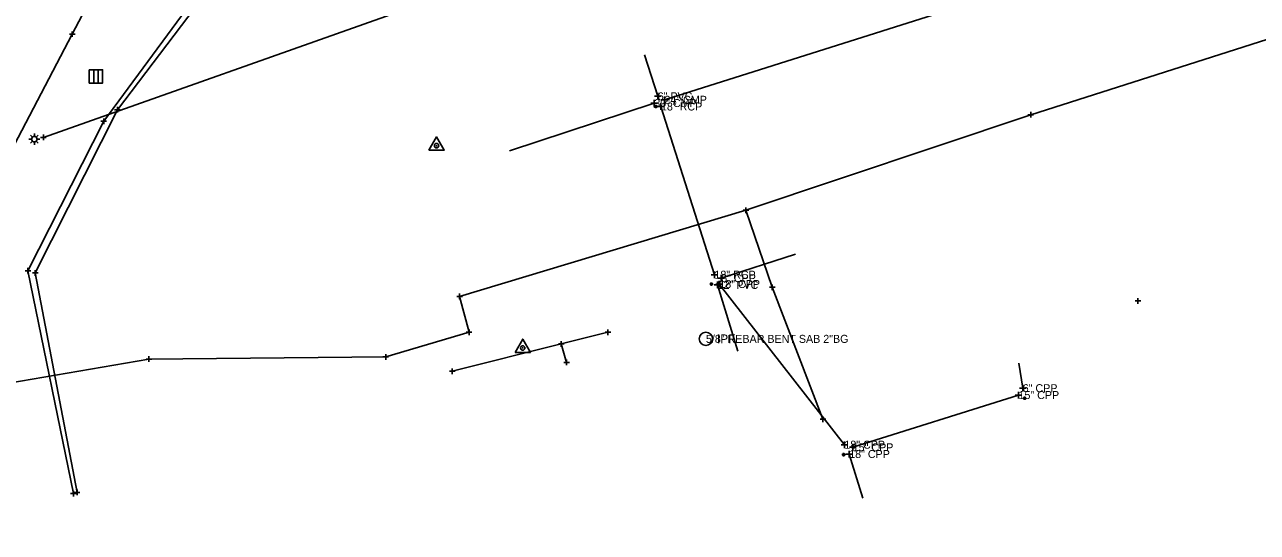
# Model space of a CAD drawing. Extents: x 1729655 to 1739338, y 463812 to 469501.
# Drawn here: x 1734846.2 to 1735123.5, y 466751 to 466865.3 of the extents above; entities that cross this region are included whole.
import ezdxf

# ---------------------------------------------------------------- set-up
doc = ezdxf.new("R2010")
doc.units = 0
for name, color, linetype in [('S_Bridge_Column_Round', 7, 'Continuous'), ('S_Bridge_Deck', 7, 'Continuous'), ('S_Bridge_ExpansionJoint', 7, 'Continuous'), ('S_Drainage_RipRap', 7, 'Continuous'), ('S_Drainage_Sump', 7, 'Continuous'), ('S_Ground_SpotElevation', 7, 'Continuous'), ('S_RetWall_Top', 7, 'Continuous'), ('S_Survey_Shot', 7, 'Continuous'), ('S_Terrain_High_Points', 7, 'Continuous'), ('S_Terrain_Holes', 7, 'Continuous'), ('S_Terrain_Voids', 7, 'Continuous'), ('S_Traffic_Posts', 7, 'Continuous'), ('S_Utilities_Pole_StreetLight', 7, 'Continuous'), ('S_Utilities_UG_Water_Gate', 7, 'Continuous')]:
    doc.layers.add(name, color=color, linetype=linetype)

msp = doc.modelspace()

# ---------------------------------------------------------------- linework, layer by layer
at = {"layer": 'S_Bridge_Column_Round'}
for p, q in [((1734856.9, 466862.56), (1734856.9, 466863.83)), ((1734856.26, 466863.2), (1734857.54, 466863.2)), ((1734856.9, 466863.2), (1734856.9, 466863.2)), ((1734867.05, 466845.54), (1734867.05, 466846.81)), ((1734863.97, 466842.96), (1734863.97, 466844.23)), ((1734866.42, 466846.17), (1734867.69, 466846.17)), ((1734867.05, 466846.17), (1734867.05, 466846.17)), ((1735071.9, 466845.05), (1735073.17, 466845.05)), ((1735072.53, 466844.42), (1735072.53, 466845.69)), ((1735072.53, 466845.05), (1735072.53, 466845.05)), ((1734863.34, 466843.59), (1734864.61, 466843.59)), ((1734863.97, 466843.59), (1734863.97, 466843.59)), ((1734849.76, 466839.95), (1734851.04, 466839.95)), ((1734850.4, 466839.31), (1734850.4, 466840.59)), ((1734850.4, 466839.95), (1734850.4, 466839.95)), ((1735007.84, 466823.53), (1735009.11, 466823.53)), ((1735007.84, 466823.53), (1735009.11, 466823.53)), ((1735008.47, 466822.89), (1735008.47, 466824.17)), ((1735008.47, 466822.89), (1735008.47, 466824.17)), ((1735008.47, 466823.53), (1735008.47, 466823.53)), ((1735008.47, 466823.53), (1735008.47, 466823.53)), ((1734846.29, 466809.92), (1734847.57, 466809.92)), ((1734846.93, 466809.28), (1734846.93, 466810.56)), ((1734846.93, 466809.92), (1734846.93, 466809.92)), ((1734847.94, 466809.42), (1734849.21, 466809.42)), ((1734848.58, 466808.79), (1734848.58, 466810.06)), ((1734848.58, 466809.42), (1734848.58, 466809.42)), ((1735013.76, 466806.21), (1735015.03, 466806.21)), ((1735014.4, 466805.57), (1735014.4, 466806.85)), ((1735014.4, 466806.21), (1735014.4, 466806.21)), ((1734943.41, 466804.13), (1734944.68, 466804.14)), ((1734944.05, 466803.5), (1734944.04, 466804.77)), ((1734944.05, 466804.13), (1734944.05, 466804.13)), ((1735096.04, 466803.1), (1735097.31, 466803.1)), ((1735096.67, 466802.46), (1735096.67, 466803.74)), ((1735096.67, 466803.1), (1735096.67, 466803.1)), ((1734945.54, 466796.06), (1734946.82, 466796.06)), ((1734946.18, 466795.43), (1734946.18, 466796.7)), ((1734946.18, 466796.06), (1734946.18, 466796.06)), ((1734976.79, 466796.06), (1734978.06, 466796.06)), ((1734977.43, 466795.42), (1734977.43, 466796.7)), ((1734977.43, 466796.06), (1734977.43, 466796.06)), ((1734966.29, 466793.42), (1734967.56, 466793.42)), ((1734966.29, 466793.42), (1734967.56, 466793.42)), ((1734966.92, 466792.78), (1734966.92, 466794.06)), ((1734966.92, 466792.78), (1734966.92, 466794.06)), ((1734966.92, 466793.42), (1734966.92, 466793.42)), ((1734966.92, 466793.42), (1734966.92, 466793.42)), ((1734873.52, 466790.03), (1734874.79, 466790.03)), ((1734874.16, 466789.39), (1734874.15, 466790.66)), ((1734874.16, 466790.03), (1734874.16, 466790.03)), ((1734926.8, 466790.5), (1734928.07, 466790.5)), ((1734927.44, 466789.86), (1734927.44, 466791.14)), ((1734927.44, 466790.5), (1734927.44, 466790.5)), ((1734967.48, 466789.28), (1734968.75, 466789.28)), ((1734968.12, 466788.65), (1734968.12, 466789.92)), ((1734968.12, 466789.28), (1734968.12, 466789.28)), ((1734941.75, 466787.27), (1734943.02, 466787.28)), ((1734942.39, 466786.64), (1734942.38, 466787.91)), ((1734942.39, 466787.28), (1734942.39, 466787.28)), ((1735025.14, 466776.48), (1735026.41, 466776.48)), ((1735025.78, 466775.84), (1735025.78, 466777.11)), ((1735025.78, 466776.48), (1735025.78, 466776.48)), ((1734856.51, 466759.71), (1734857.78, 466759.71)), ((1734857.15, 466759.07), (1734857.15, 466760.34)), ((1734857.15, 466759.71), (1734857.15, 466759.71)), ((1734857.36, 466759.99), (1734858.63, 466759.99)), ((1734858, 466759.35), (1734858, 466760.62)), ((1734858, 466759.99), (1734858, 466759.99))]:
    msp.add_line(p, q, dxfattribs=at)
at = {"layer": 'S_Bridge_Deck'}
for p, q in [((1734847.75, 466839.54), (1734847.13, 466839.54)), ((1734847.93, 466839.98), (1734847.49, 466840.42)), ((1734847.93, 466839.1), (1734847.49, 466838.66)), ((1734848.37, 466840.16), (1734848.37, 466840.79)), ((1734848.37, 466838.92), (1734848.37, 466838.29)), ((1734848.81, 466839.98), (1734849.26, 466840.42)), ((1734848.81, 466839.1), (1734849.26, 466838.66)), ((1734849, 466839.54), (1734849.62, 466839.54))]:
    msp.add_line(p, q, dxfattribs=at)
msp.add_circle((1734848.37, 466839.54), 0.624, dxfattribs=at)
at = {"layer": 'S_Bridge_ExpansionJoint'}
for p, q in [((1734988.62, 466849.95), (1734988.62, 466848.45)), ((1734987.1, 466847.68), (1734988.6, 466847.68)), ((1734987.85, 466848.43), (1734987.85, 466846.93)), ((1734987.87, 466849.2), (1734989.37, 466849.2)), ((1734988.6, 466846.91), (1734990.1, 466846.91)), ((1734989.35, 466847.66), (1734989.35, 466846.16)), ((1734989.38, 466848.42), (1734990.88, 466848.42)), ((1734990.13, 466849.17), (1734990.13, 466847.67)), ((1735000.63, 466809.02), (1735002.13, 466809.02)), ((1735001.38, 466809.77), (1735001.38, 466808.27)), ((1735002.14, 466808.24), (1735003.64, 466808.24)), ((1735002.89, 466808.99), (1735002.89, 466807.49)), ((1735001.35, 466806.72), (1735002.85, 466806.72)), ((1735001.73, 466806.92), (1735003.23, 466806.92)), ((1735002.1, 466807.47), (1735002.1, 466805.97)), ((1735002.48, 466807.67), (1735002.48, 466806.17)), ((1735069.99, 466783.46), (1735071.49, 466783.46)), ((1735070.74, 466784.21), (1735070.74, 466782.71)), ((1735069.04, 466781.91), (1735070.54, 466781.91)), ((1735069.79, 466782.66), (1735069.79, 466781.16)), ((1735029.86, 466770.73), (1735031.36, 466770.73)), ((1735030.61, 466771.48), (1735030.61, 466769.98)), ((1735031.7, 466769.38), (1735031.7, 466767.88)), ((1735031.74, 466770.14), (1735033.24, 466770.14)), ((1735032.49, 466770.89), (1735032.49, 466769.39)), ((1735030.95, 466768.63), (1735032.45, 466768.63))]:
    msp.add_line(p, q, dxfattribs=at)
at = {"layer": 'S_Drainage_RipRap'}
for p, q in [((1734861.74, 466855.17), (1734861.74, 466852.18)), ((1734862.74, 466855.17), (1734862.74, 466852.18))]:
    msp.add_line(p, q, dxfattribs=at)
msp.add_lwpolyline([(1734860.74, 466855.17), (1734863.74, 466855.17), (1734863.74, 466852.18), (1734860.74, 466852.18)], close=True, dxfattribs=at)
at = {"layer": 'S_Drainage_Sump'}
for p, q in [((1734988.55, 466846.91), (1734987.77, 466846.91)), ((1734988.42, 466846.64), (1734987.9, 466847.17)), ((1734988.42, 466847.17), (1734987.9, 466846.64)), ((1734988.16, 466847.3), (1734988.16, 466846.51)), ((1735001.11, 466806.89), (1735000.32, 466806.89)), ((1735000.98, 466806.63), (1735000.45, 466807.16)), ((1735000.98, 466807.16), (1735000.45, 466806.63)), ((1735000.71, 466807.29), (1735000.71, 466806.5)), ((1735071.55, 466781.19), (1735070.77, 466781.19)), ((1735071.42, 466780.93), (1735070.9, 466781.46)), ((1735071.42, 466781.46), (1735070.9, 466780.93)), ((1735071.16, 466781.59), (1735071.16, 466780.8)), ((1735030.83, 466768.5), (1735030.04, 466768.5)), ((1735030.7, 466768.24), (1735030.17, 466768.76)), ((1735030.7, 466768.76), (1735030.17, 466768.24)), ((1735030.44, 466768.89), (1735030.44, 466768.11))]:
    msp.add_line(p, q, dxfattribs=at)
at = {"layer": 'S_Ground_SpotElevation'}
msp.add_lwpolyline([(1734843.85, 466838.23), (1734856.9, 466863.2), (1734876.52, 466900.68), (1734888.39, 466923.54)], dxfattribs=at)
at = {"layer": 'S_RetWall_Top'}
for p, q in [((1735216.98, 466920.25), (1734990.13, 466848.42)), ((1734985.61, 466858.54), (1734988.62, 466849.2)), ((1734987.85, 466847.68), (1734955.24, 466836.94)), ((1735001.38, 466809.02), (1734989.35, 466846.91)), ((1735019.63, 466813.64), (1735002.89, 466808.24)), ((1735006.67, 466791.82), (1735002.1, 466806.72)), ((1735030.61, 466770.73), (1735002.48, 466806.92)), ((1735069.83, 466789.1), (1735070.74, 466783.46)), ((1735069.79, 466781.91), (1735032.49, 466770.14)), ((1735034.77, 466758.68), (1735031.7, 466768.63))]:
    msp.add_line(p, q, dxfattribs=at)
at = {"layer": 'S_Survey_Shot'}
for points in [[(1734707.61, 466750.98), (1734729.87, 466756.78), (1734757.67, 466764.32), (1734786.28, 466774.83), (1734800.4, 466776.99), (1734803.2, 466777.8), (1734874.16, 466790.03), (1734927.44, 466790.5), (1734946.18, 466796.06), (1734944.05, 466804.13), (1735008.47, 466823.53), (1735072.53, 466845.05), (1735244.51, 466900.06), (1735283.23, 466909.39), (1735327.94, 466925.11), (1735706.87, 467043.8)], [(1735008.47, 466823.53), (1735014.4, 466806.21), (1735025.78, 466776.48)]]:
    msp.add_lwpolyline(points, dxfattribs=at)
at = {"layer": 'S_Terrain_Holes'}
msp.add_circle((1734999.46, 466794.57), 1.5, dxfattribs=at)
at = {"layer": 'S_Terrain_Voids'}
for p, q in [((1734938.73, 466838.08), (1734938.98, 466838.08)), ((1734938.86, 466838.2), (1734938.86, 466837.95)), ((1734958.12, 466792.52), (1734958.37, 466792.52)), ((1734958.25, 466792.64), (1734958.25, 466792.39))]:
    msp.add_line(p, q, dxfattribs=at)
for points in [[(1734937.13, 466837.08), (1734940.59, 466837.08), (1734938.86, 466840.07)], [(1734956.52, 466791.52), (1734959.98, 466791.52), (1734958.25, 466794.52)]]:
    msp.add_lwpolyline(points, close=True, dxfattribs=at)
for centre in [(1734938.86, 466838.08), (1734958.25, 466792.52)]:
    msp.add_circle(centre, 0.499, dxfattribs=at)
at = {"layer": 'S_Traffic_Posts'}
msp.add_lwpolyline([(1734858, 466759.99), (1734848.58, 466809.42), (1734867.05, 466846.17), (1734910.08, 466902.93)], dxfattribs=at)
at = {"layer": 'S_Utilities_Pole_StreetLight'}
for points in [[(1735055.65, 466913.55), (1734995.12, 466893.79), (1734932.25, 466868.87), (1734850.4, 466839.95)], [(1734857.15, 466759.71), (1734846.93, 466809.92), (1734863.97, 466843.59), (1734909.07, 466904.86)]]:
    msp.add_lwpolyline(points, dxfattribs=at)
at = {"layer": 'S_Utilities_UG_Water_Gate'}
for points in [[(1734977.43, 466796.06), (1734966.92, 466793.42), (1734942.39, 466787.28)], [(1734966.92, 466793.42), (1734968.12, 466789.28)]]:
    msp.add_lwpolyline(points, dxfattribs=at)

# ---------------------------------------------------------------- texts
at = {"layer": 'S_Terrain_High_Points'}
for s, p in [('6" PVC', (1734988.62, 466848.3)), ('30" CMP', (1734987.85, 466846.78)), ('18" RCP', (1734989.35, 466846.01)), ('24" CMP', (1734990.13, 466847.52)), ('18" RCP', (1735001.38, 466808.12)), ('6" CPP', (1735002.89, 466807.34)), ('12" PVC', (1735002.1, 466805.82)), ('18" CPP', (1735002.48, 466806.02)), ('5/8" REBAR BENT SAB 2"BG', (1734999.46, 466793.67)), ('6" CPP', (1735070.74, 466782.56)), ('15" CPP', (1735069.79, 466781.01)), ('18" CPP', (1735030.61, 466769.83)), ('18" CPP', (1735031.7, 466767.73)), ('15" CPP', (1735032.49, 466769.24))]:
    msp.add_text(s, height=1.8, dxfattribs=at).set_placement(p)
at = {"layer": 'S_Terrain_Holes'}
msp.add_text('IPF', height=1.996, dxfattribs=at).set_placement((1735001.96, 466793.57))

doc.saveas('drawing.dxf')
